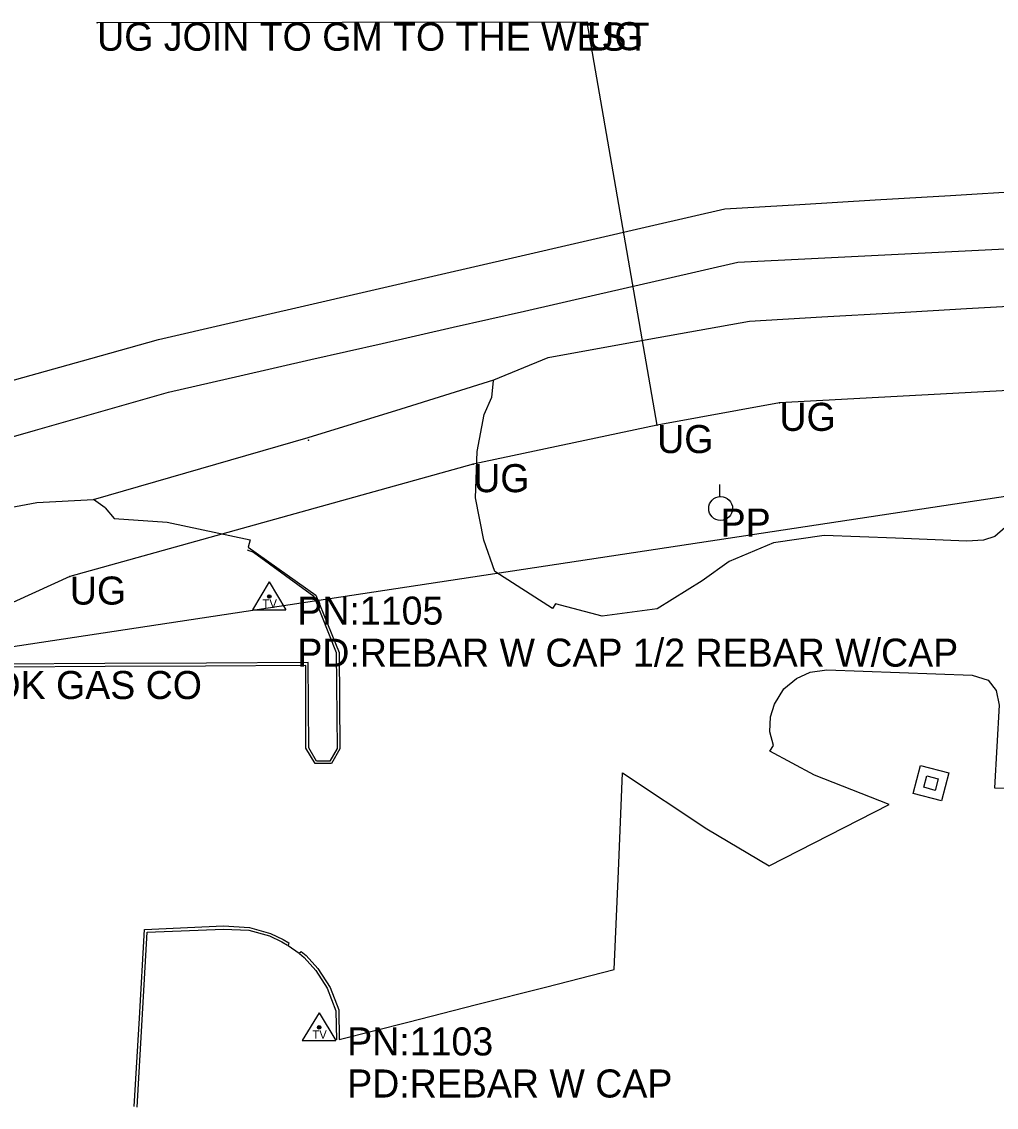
# Model space of a CAD drawing. Extents: x 675481 to 678499, y 212715 to 215285.
# Drawn here: x 678052.3 to 678226, y 214440.8 to 214634.3 of the extents above; entities that cross this region are included whole.
import ezdxf

# ---------------------------------------------------------------- set-up
doc = ezdxf.new("R2010")
doc.units = 0
for name, color, linetype in [('S_CURB', 7, 'Continuous'), ('S_EDGE_CONCRETE', 7, 'Continuous'), ('S_EDGE_PAVEMENT', 7, 'Continuous'), ('S_GAS_UTILITIES', 7, 'Continuous'), ('S_GAS_UTILITIES_ANNOT', 7, 'Continuous'), ('S_GRD_PT_SYM', 7, 'Continuous'), ('S_PAVEMENT_CROWN', 7, 'Continuous'), ('S_SECONDARY_CTL', 7, 'Continuous'), ('S_SECONDARY_CTL_ANNOT', 7, 'Continuous'), ('S_UNDERGROUND_CABLE', 7, 'Continuous'), ('S_UTILITY_POLE', 7, 'Continuous'), ('S_UTILITY_POLE_ANNOT', 7, 'Continuous'), ('S_UTL_PT_SYM', 7, 'Continuous')]:
    doc.layers.add(name, color=color, linetype=linetype)

msp = doc.modelspace()

# ---------------------------------------------------------------- linework, layer by layer
at = {"layer": 'S_CURB'}
for points in [[(678092.45, 214540.14), (678093.58, 214539.75), (678104.35, 214531.9), (678108.34, 214521.82), (678108.47, 214504.73), (678107.2, 214502.5), (678104.79, 214502.5), (678103.42, 214504.84), (678103.34, 214520.06), (678085.22, 214519.97), (678067.09, 214519.88), (678048.97, 214519.79)], [(678072.83, 214440.77), (678073.72, 214456.36), (678074.62, 214471.96), (678088.25, 214472.54), (678092.75, 214472.32), (678096.41, 214471.32), (678098.6, 214470.29), (678099.65, 214469.65)], [(678101.78, 214468.21), (678102.6, 214467.47), (678104.68, 214465.17), (678106.73, 214462.03), (678108.26, 214457.99), (678108.37, 214452.8)]]:
    msp.add_lwpolyline(points, dxfattribs=at)
at = {"layer": 'S_EDGE_CONCRETE'}
for points in [[(678227.52, 214544.13), (678225.69, 214542.52), (678223.66, 214541.87), (678220.7, 214541.72), (678207.98, 214542.22), (678195.27, 214542.71), (678186.25, 214541.4), (678178.34, 214538.08), (678173.52, 214534.65), (678165.51, 214529.66), (678155.69, 214528.33), (678147.38, 214530.55), (678146.84, 214529.7), (678136.6, 214536.29), (678134.6, 214541.86), (678133.17, 214549.42), (678133.42, 214557.7), (678134.66, 214564.29), (678136.04, 214567.37), (678136.37, 214570.3)], [(678136.37, 214570.3), (678136.44, 214570.43)], [(678067.14, 214547.66), (678065.07, 214549.15)], [(678067.14, 214547.66), (678068.77, 214545.73), (678078.18, 214545.09), (678092.98, 214541.94), (678092.99, 214541.92), (678092.61, 214540.63), (678104.71, 214532.09), (678108.84, 214521.82), (678108.96, 214504.7), (678107.47, 214502.07), (678104.56, 214502.05), (678102.9, 214504.79), (678102.88, 214519.51), (678085.01, 214519.42), (678067.14, 214519.33), (678049.27, 214519.23)], [(678072.34, 214440.91), (678073.26, 214456.67), (678074.18, 214472.44), (678088.22, 214473.11), (678092.89, 214472.83), (678096.63, 214471.74), (678098.89, 214470.7), (678099.9, 214470.06), (678099.75, 214469.61), (678101.71, 214468.23), (678102.05, 214468.53), (678102.95, 214467.83), (678105.06, 214465.51), (678107.24, 214462.14), (678108.76, 214458.13), (678108.86, 214452.85), (678121.1, 214455.97), (678133.35, 214459.09), (678145.59, 214462.21), (678157.84, 214465.32), (678158.61, 214482.85), (678159.37, 214500.37), (678174.36, 214490.39), (678185.47, 214483.81), (678206.89, 214494.75), (678193.55, 214499.98), (678185.62, 214504.28), (678186.25, 214505.24), (678185.59, 214507.69), (678185.74, 214510.39), (678186.41, 214512.63), (678188.09, 214515.4), (678190.33, 214517.23), (678192.78, 214518.32), (678195.74, 214518.73), (678208.71, 214518.26), (678221.68, 214517.8), (678224.49, 214516.92), (678225.95, 214515.05), (678226.45, 214512.47), (678225.63, 214497.7), (678249.55, 214496.86)]]:
    msp.add_lwpolyline(points, dxfattribs=at)
for points in [[(678211.12, 214496.71), (678212.45, 214501.72), (678217.51, 214500.42), (678216.18, 214495.43)], [(678213.03, 214497.81), (678213.57, 214499.86), (678215.61, 214499.33), (678215.09, 214497.27)]]:
    msp.add_lwpolyline(points, close=True, dxfattribs=at)
at = {"layer": 'S_EDGE_PAVEMENT'}
for points in [[(678040.42, 214567.48), (678052.5, 214570.87), (678064.57, 214574.26), (678076.65, 214577.65), (678089.26, 214580.57), (678101.88, 214583.48), (678114.49, 214586.39), (678127.11, 214589.3), (678139.72, 214592.21), (678152.34, 214595.12), (678164.95, 214598.03), (678177.57, 214600.94), (678190.97, 214601.74), (678204.38, 214602.54), (678217.78, 214603.34), (678231.18, 214604.14)], [(678035.25, 214544.88), (678054.98, 214548.6), (678065.07, 214549.15), (678084.19, 214554.65), (678103.3, 214560.15), (678119.87, 214565.29), (678136.44, 214570.43), (678146.12, 214574.43), (678164.06, 214577.68), (678182, 214580.93), (678194.88, 214581.67), (678207.75, 214582.41), (678220.63, 214583.15), (678233.5, 214583.9)]]:
    msp.add_lwpolyline(points, dxfattribs=at)
at = {"layer": 'S_GAS_UTILITIES'}
for p, q in [((678153.06, 214634.23), (678065.71, 214634.13)), ((678165.51, 214562.4), (678153.06, 214634.23)), ((678310.98, 214573.01), (678187.31, 214566.36)), ((678187.31, 214566.36), (678165.51, 214562.4)), ((678165.51, 214562.4), (678132.73, 214555.43)), ((678132.73, 214555.43), (678060.85, 214535.39)), ((678060.85, 214535.39), (678023.84, 214518.55))]:
    msp.add_line(p, q, dxfattribs=at)
at = {"layer": 'S_GRD_PT_SYM'}
msp.add_lwpolyline([(678103.4, 214559.71), (678103.4, 214559.76), (678103.4, 214559.71), (678103.35, 214559.71), (678103.4, 214559.71), (678103.4, 214559.66), (678103.4, 214559.71), (678103.45, 214559.71)], dxfattribs=at)
at = {"layer": 'S_PAVEMENT_CROWN'}
msp.add_lwpolyline([(677889.42, 214508.16), (677912.41, 214516.17), (677935.39, 214524.19), (677947.44, 214528.42), (677959.49, 214532.65), (677971.54, 214536.88), (677983.58, 214541.1), (678007.3, 214547.9), (678031.02, 214554.69), (678054.74, 214561.49), (678078.45, 214568.28), (678091.14, 214571.17), (678103.82, 214574.06), (678116.5, 214576.95), (678129.18, 214579.84), (678141.86, 214582.73), (678154.54, 214585.62), (678167.23, 214588.52), (678179.91, 214591.41), (678193.01, 214592.07), (678206.1, 214592.74), (678219.2, 214593.4), (678232.3, 214594.07)], dxfattribs=at)
at = {"layer": 'S_SECONDARY_CTL'}
for p, q in [((678096.39, 214534.43), (678093.38, 214529.48)), ((678096.39, 214534.43), (678099.34, 214529.48)), ((678093.38, 214529.48), (678099.34, 214529.48)), ((678105.28, 214457.62), (678102.27, 214452.66)), ((678105.28, 214457.62), (678108.23, 214452.66)), ((678102.27, 214452.66), (678108.23, 214452.66))]:
    msp.add_line(p, q, dxfattribs=at)
for centre, radius in [((678096.39, 214531.82), 0.311), ((678096.39, 214531.82), 0.183), ((678096.39, 214531.82), 0.103), ((678105.28, 214455.01), 0.311), ((678105.28, 214455.01), 0.183), ((678105.28, 214455.01), 0.103)]:
    msp.add_circle(centre, radius, dxfattribs=at)
at = {"layer": 'S_UNDERGROUND_CABLE'}
msp.add_line((678313.93, 214562.77), (678000.75, 214515.3), dxfattribs=at)
at = {"layer": 'S_UTILITY_POLE'}
msp.add_line((678176.71, 214549.66), (678176.71, 214551.77), dxfattribs=at)
msp.add_circle((678176.83, 214547.52), 2.13, dxfattribs=at)
at = {"layer": 'S_UTL_PT_SYM'}
for points in [[(678065.71, 214634.13), (678065.71, 214634.18), (678065.71, 214634.13), (678065.66, 214634.13), (678065.71, 214634.13), (678065.71, 214634.08), (678065.71, 214634.13), (678065.77, 214634.13)], [(678153.06, 214634.23), (678153.06, 214634.28), (678153.06, 214634.23), (678153.01, 214634.23), (678153.06, 214634.23), (678153.06, 214634.18), (678153.06, 214634.23), (678153.11, 214634.23)], [(678187.31, 214566.36), (678187.31, 214566.41), (678187.31, 214566.36), (678187.26, 214566.36), (678187.31, 214566.36), (678187.31, 214566.31), (678187.31, 214566.36), (678187.36, 214566.36)], [(678165.51, 214562.4), (678165.51, 214562.45), (678165.51, 214562.4), (678165.46, 214562.4), (678165.51, 214562.4), (678165.51, 214562.35), (678165.51, 214562.4), (678165.56, 214562.4)], [(678165.51, 214562.4), (678165.51, 214562.45), (678165.51, 214562.4), (678165.46, 214562.4), (678165.51, 214562.4), (678165.51, 214562.35), (678165.51, 214562.4), (678165.56, 214562.4)], [(678132.73, 214555.43), (678132.73, 214555.48), (678132.73, 214555.43), (678132.68, 214555.43), (678132.73, 214555.43), (678132.73, 214555.38), (678132.73, 214555.43), (678132.79, 214555.43)], [(678060.85, 214535.39), (678060.85, 214535.43), (678060.85, 214535.39), (678060.8, 214535.39), (678060.85, 214535.39), (678060.85, 214535.34), (678060.85, 214535.39), (678060.9, 214535.39)]]:
    msp.add_lwpolyline(points, dxfattribs=at)

# ---------------------------------------------------------------- texts
at = {"layer": 'S_GAS_UTILITIES_ANNOT'}
for s, p in [('UG JOIN TO GM TO THE WEST', (678065.71, 214629.13)), ('UG', (678153.06, 214629.23)), ('UG', (678187.31, 214561.36)), ('UG', (678165.51, 214557.4)), ('UG', (678165.51, 214557.4)), ('UG', (678132.73, 214550.43)), ('UG', (678060.85, 214530.39)), ('UG AR OK GAS CO', (678023.84, 214513.55)), ('UG AR OK GAS CO', (678023.84, 214513.55))]:
    msp.add_text(s, height=5, dxfattribs=at).set_placement(p)
at = {"layer": 'S_SECONDARY_CTL'}
for p in [(678095.19, 214529.81), (678104.08, 214453)]:
    msp.add_text('TV', height=1.5, rotation=360, dxfattribs=at).set_placement(p)
at = {"layer": 'S_SECONDARY_CTL_ANNOT'}
for s, p in [('PN:1105', (678101.39, 214526.82)), ('PD:REBAR W CAP 1/2 REBAR W/CAP', (678101.39, 214519.32)), ('PN:1103', (678110.28, 214450.01)), ('PD:REBAR W CAP', (678110.28, 214442.51))]:
    msp.add_text(s, height=5, dxfattribs=at).set_placement(p)
at = {"layer": 'S_UTILITY_POLE_ANNOT'}
msp.add_text('PP', height=5, dxfattribs=at).set_placement((678176.83, 214542.52))

doc.saveas('drawing.dxf')
